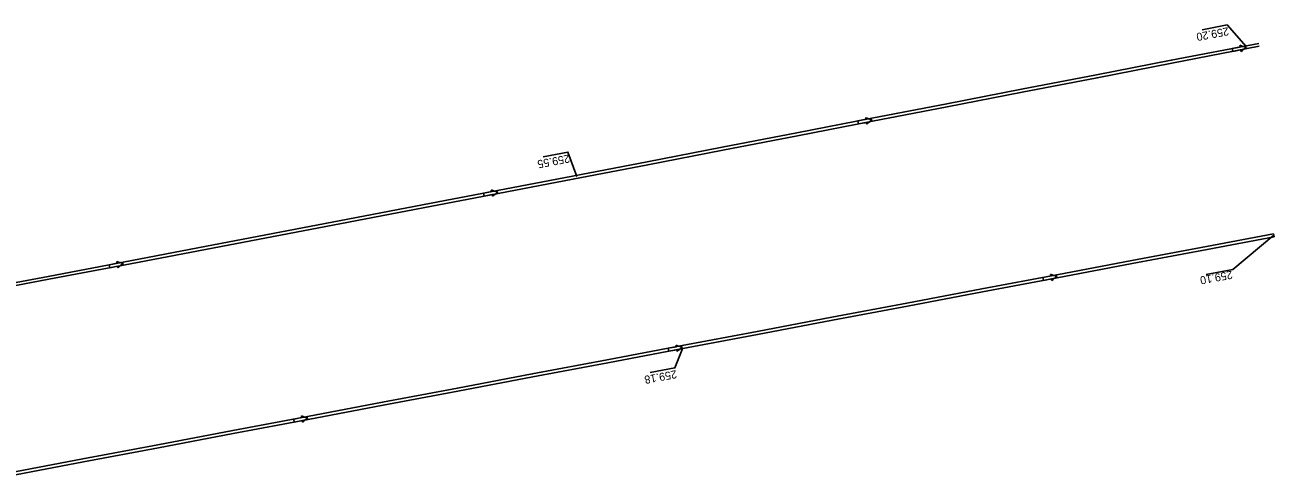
# Model space of a CAD drawing. Extents: x -1 to 65640748, y -22 to 5530284.
# Drawn here: x 6559133.8 to 6559297.7, y 5528984.5 to 5529043.7 of the extents above; entities that cross this region are included whole.
import ezdxf

# ---------------------------------------------------------------- set-up
doc = ezdxf.new("R2010")
doc.units = 0
for name, color, linetype in [('TOR_PS_OPIS_O-opisy rurociagow', 7, 'Continuous'), ('TOR_PS_OPIS_T-INFO', 7, 'Continuous'), ('TOR_PS_T-rowy otwarte umocnione', 7, 'Continuous')]:
    doc.layers.add(name, color=color, linetype=linetype)

msp = doc.modelspace()

# ---------------------------------------------------------------- linework, layer by layer
at = {"layer": 'TOR_PS_OPIS_O-opisy rurociagow'}
for p, q in [((6559293.24, 5529040.86), (6559292.17, 5529040.65)), ((6559293.24, 5529040.86), (6559292.17, 5529040.65)), ((6559292.17, 5529040.65), (6559292.24, 5529040.26)), ((6559292.17, 5529040.65), (6559292.24, 5529040.26)), ((6559292.24, 5529040.26), (6559293.32, 5529040.46)), ((6559293.32, 5529040.46), (6559292.24, 5529040.26)), ((6559244.15, 5529031.35), (6559243.08, 5529031.14)), ((6559244.15, 5529031.35), (6559243.08, 5529031.14)), ((6559243.08, 5529031.14), (6559243.16, 5529030.75)), ((6559243.08, 5529031.14), (6559243.16, 5529030.75)), ((6559243.16, 5529030.75), (6559244.23, 5529030.95)), ((6559244.23, 5529030.95), (6559243.16, 5529030.75)), ((6559195.06, 5529021.86), (6559193.99, 5529021.66)), ((6559195.06, 5529021.86), (6559193.99, 5529021.66)), ((6559193.99, 5529021.66), (6559194.06, 5529021.27)), ((6559193.99, 5529021.66), (6559194.06, 5529021.27)), ((6559194.06, 5529021.27), (6559195.13, 5529021.47)), ((6559195.13, 5529021.47), (6559194.06, 5529021.27)), ((6559145.95, 5529012.48), (6559144.88, 5529012.27)), ((6559145.95, 5529012.48), (6559144.88, 5529012.27)), ((6559144.88, 5529012.27), (6559144.95, 5529011.88)), ((6559144.88, 5529012.27), (6559144.95, 5529011.88)), ((6559144.95, 5529011.88), (6559146.02, 5529012.08)), ((6559146.02, 5529012.08), (6559144.95, 5529011.88)), ((6559268.41, 5529010.8), (6559267.33, 5529010.6)), ((6559268.41, 5529010.8), (6559267.33, 5529010.6)), ((6559267.33, 5529010.6), (6559267.41, 5529010.21)), ((6559267.33, 5529010.6), (6559267.41, 5529010.21)), ((6559267.41, 5529010.21), (6559268.48, 5529010.41)), ((6559268.48, 5529010.41), (6559267.41, 5529010.21)), ((6559219.28, 5529001.51), (6559218.2, 5529001.3)), ((6559219.28, 5529001.51), (6559218.2, 5529001.3)), ((6559218.2, 5529001.3), (6559218.28, 5529000.91)), ((6559218.2, 5529001.3), (6559218.28, 5529000.91)), ((6559218.28, 5529000.91), (6559219.35, 5529001.11)), ((6559219.35, 5529001.11), (6559218.28, 5529000.91)), ((6559170.15, 5528992.22), (6559169.08, 5528992.01)), ((6559170.15, 5528992.22), (6559169.08, 5528992.01)), ((6559169.08, 5528992.01), (6559169.15, 5528991.62)), ((6559169.08, 5528992.01), (6559169.15, 5528991.62)), ((6559169.15, 5528991.62), (6559170.22, 5528991.82)), ((6559170.22, 5528991.82), (6559169.15, 5528991.62))]:
    msp.add_line(p, q, dxfattribs=at)
for points in [[(6559293.19, 5529041.08), (6559293.19, 5529041.08)], [(6559293.35, 5529040.24), (6559293.35, 5529040.24)], [(6559244.1, 5529031.56), (6559244.1, 5529031.56)], [(6559244.26, 5529030.73), (6559244.26, 5529030.73)], [(6559195.01, 5529022.08), (6559195.01, 5529022.08)], [(6559195.17, 5529021.25), (6559195.17, 5529021.25)], [(6559145.9, 5529012.69), (6559145.9, 5529012.69)], [(6559146.06, 5529011.86), (6559146.06, 5529011.86)], [(6559268.35, 5529011.02), (6559268.35, 5529011.02)], [(6559268.51, 5529010.19), (6559268.51, 5529010.19)], [(6559219.23, 5529001.73), (6559219.23, 5529001.73)], [(6559219.38, 5529000.89), (6559219.38, 5529000.89)], [(6559170.1, 5528992.44), (6559170.1, 5528992.44)], [(6559170.25, 5528991.6), (6559170.25, 5528991.6)]]:
    msp.add_lwpolyline(points, dxfattribs=at)
for centre, radius, start, end in [((6559295.09, 5529045.61), 4.92, 247.2552, 257.637), ((6559293.64, 5529041.07), 0.458, 179.3698, 207.831), ((6559295.09, 5529045.61), 4.92, 247.2552, 257.637), ((6559293.64, 5529041.07), 0.458, 179.3698, 207.831), ((6559296.81, 5529036.74), 4.92, 124.2931, 134.6749), ((6559296.81, 5529036.74), 4.92, 124.2931, 134.6749), ((6559293.77, 5529040.42), 0.458, 174.0991, 202.5603), ((6559293.77, 5529040.42), 0.458, 174.0991, 202.5603), ((6559246, 5529036.1), 4.92, 247.2552, 257.637), ((6559244.56, 5529031.56), 0.458, 179.3698, 207.831), ((6559246, 5529036.1), 4.92, 247.2552, 257.637), ((6559244.56, 5529031.56), 0.458, 179.3698, 207.831), ((6559244.68, 5529030.91), 0.458, 174.0991, 202.5603), ((6559244.68, 5529030.91), 0.458, 174.0991, 202.5603), ((6559247.72, 5529027.23), 4.92, 124.2931, 134.6749), ((6559247.72, 5529027.23), 4.92, 124.2931, 134.6749), ((6559196.92, 5529026.61), 4.92, 247.1116, 257.4934), ((6559195.46, 5529022.08), 0.458, 179.2261, 207.6874), ((6559196.92, 5529026.61), 4.92, 247.1116, 257.4934), ((6559195.46, 5529022.08), 0.458, 179.2261, 207.6874), ((6559195.59, 5529021.42), 0.458, 173.9555, 202.4167), ((6559195.59, 5529021.42), 0.458, 173.9555, 202.4167), ((6559198.62, 5529017.74), 4.92, 124.1495, 134.5313), ((6559198.62, 5529017.74), 4.92, 124.1495, 134.5313), ((6559147.81, 5529017.23), 4.92, 247.1116, 257.4934), ((6559146.35, 5529012.69), 0.458, 179.2261, 207.6874), ((6559147.81, 5529017.23), 4.92, 247.1116, 257.4934), ((6559146.35, 5529012.69), 0.458, 179.2261, 207.6874), ((6559146.48, 5529012.03), 0.458, 173.9555, 202.4167), ((6559146.48, 5529012.03), 0.458, 173.9555, 202.4167), ((6559149.5, 5529008.35), 4.92, 124.1495, 134.5313), ((6559149.5, 5529008.35), 4.92, 124.1495, 134.5313), ((6559270.28, 5529015.55), 4.92, 247.0039, 257.3858), ((6559268.81, 5529011.01), 0.458, 179.1185, 207.5797), ((6559270.28, 5529015.55), 4.92, 247.0039, 257.3858), ((6559268.81, 5529011.01), 0.458, 179.1185, 207.5797), ((6559268.94, 5529010.36), 0.458, 173.8478, 202.3091), ((6559268.94, 5529010.36), 0.458, 173.8478, 202.3091), ((6559271.95, 5529006.67), 4.92, 124.0418, 134.4236), ((6559271.95, 5529006.67), 4.92, 124.0418, 134.4236), ((6559221.15, 5529006.25), 4.92, 247.0039, 257.3858), ((6559219.68, 5529001.72), 0.458, 179.1185, 207.5797), ((6559221.15, 5529006.25), 4.92, 247.0039, 257.3858), ((6559219.68, 5529001.72), 0.458, 179.1185, 207.5797), ((6559222.83, 5528997.38), 4.92, 124.0418, 134.4236), ((6559222.83, 5528997.38), 4.92, 124.0418, 134.4236), ((6559219.81, 5529001.07), 0.458, 173.8478, 202.3091), ((6559219.81, 5529001.07), 0.458, 173.8478, 202.3091), ((6559172.02, 5528996.96), 4.92, 246.9983, 257.3802), ((6559170.55, 5528992.43), 0.458, 179.1129, 207.5741), ((6559172.02, 5528996.96), 4.92, 246.9983, 257.3802), ((6559170.55, 5528992.43), 0.458, 179.1129, 207.5741), ((6559170.68, 5528991.78), 0.458, 173.8423, 202.3035), ((6559170.68, 5528991.78), 0.458, 173.8423, 202.3035), ((6559173.7, 5528988.09), 4.92, 124.0362, 134.4181), ((6559173.7, 5528988.09), 4.92, 124.0362, 134.4181)]:
    msp.add_arc(centre, radius, start, end, dxfattribs=at)
at = {"layer": 'TOR_PS_OPIS_T-INFO'}
for points in [[(6559294, 5529040.89), (6559291.49, 5529043.73), (6559288.25, 5529043.11)], [(6559206.2, 5529023.84), (6559205.05, 5529027.04), (6559201.82, 5529026.42)], [(6559297.62, 5529016.13), (6559292.24, 5529011.64), (6559288.76, 5529011)], [(6559220.1, 5529001.38), (6559219.09, 5528998.73), (6559215.85, 5528998.11)]]:
    msp.add_lwpolyline(points, dxfattribs=at)
at = {"layer": 'TOR_PS_T-rowy otwarte umocnione'}
for points in [[(6559295.65, 5529041.32), (6559284.18, 5529039.1), (6559274.36, 5529037.2), (6559264.54, 5529035.3), (6559254.73, 5529033.39), (6559244.91, 5529031.49), (6559235.09, 5529029.59), (6559225.27, 5529027.69), (6559215.46, 5529025.79), (6559205.64, 5529023.89), (6559195.82, 5529022.01), (6559185.99, 5529020.13), (6559176.17, 5529018.25), (6559166.35, 5529016.38), (6559156.53, 5529014.5), (6559146.71, 5529012.62), (6559136.88, 5529010.74), (6559127.06, 5529008.87)], [(6559295.72, 5529040.93), (6559284.25, 5529038.71), (6559274.44, 5529036.81), (6559264.62, 5529034.9), (6559254.8, 5529033), (6559244.98, 5529031.1), (6559235.17, 5529029.2), (6559225.35, 5529027.3), (6559215.53, 5529025.39), (6559205.71, 5529023.49), (6559195.89, 5529021.61), (6559186.07, 5529019.74), (6559176.25, 5529017.86), (6559166.42, 5529015.98), (6559156.6, 5529014.1), (6559146.78, 5529012.23), (6559136.96, 5529010.35), (6559127.14, 5529008.47)], [(6559297.58, 5529016.32), (6559288.81, 5529014.66), (6559278.99, 5529012.8), (6559269.16, 5529010.95), (6559259.33, 5529009.09), (6559249.51, 5529007.23), (6559239.68, 5529005.37), (6559229.86, 5529003.51), (6559220.03, 5529001.65), (6559210.21, 5528999.79), (6559200.38, 5528997.93), (6559190.55, 5528996.08), (6559180.73, 5528994.22), (6559170.9, 5528992.36), (6559161.08, 5528990.5), (6559151.25, 5528988.64), (6559141.42, 5528986.79), (6559131.6, 5528984.93)], [(6559297.58, 5529016.32), (6559297.66, 5529015.93), (6559288.89, 5529014.27), (6559279.06, 5529012.41), (6559269.23, 5529010.55), (6559259.41, 5529008.69), (6559249.58, 5529006.83), (6559239.76, 5529004.98), (6559229.93, 5529003.12), (6559220.11, 5529001.26), (6559210.28, 5528999.4), (6559200.45, 5528997.54), (6559190.63, 5528995.68), (6559180.8, 5528993.83), (6559170.98, 5528991.97), (6559161.15, 5528990.11), (6559151.33, 5528988.25), (6559141.5, 5528986.39), (6559131.67, 5528984.53)]]:
    msp.add_lwpolyline(points, dxfattribs=at)

# ---------------------------------------------------------------- texts
at = {"layer": 'TOR_PS_OPIS_T-INFO'}
for s, p in [('259.20', (6559291.62, 5529043.44)), ('259.55', (6559205.19, 5529026.74)), ('259.10', (6559292.1, 5529011.49)), ('259.18', (6559219.22, 5528998.44))]:
    msp.add_text(s, height=1.05, rotation=190.7159, dxfattribs=at).set_placement(p)

doc.saveas('drawing.dxf')
